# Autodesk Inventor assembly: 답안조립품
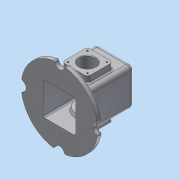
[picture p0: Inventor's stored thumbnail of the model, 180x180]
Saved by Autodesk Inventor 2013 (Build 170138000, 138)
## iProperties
Created: 2018-07
Part Number: 답안조립품
Document SubType Name: Assembly
Designer: Administrator
Author: Administrator
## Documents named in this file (2)
- C:\Users\Administrator\Desktop\480708V1011\답안조립품.iam
- C:\Users\Administrator\Desktop\480708V1011\본체.ipt
